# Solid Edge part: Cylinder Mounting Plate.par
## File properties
Author: davee
Template: Normal.par
Last saved by: davee
Revision: 2
Application: Solid Edge
Accuracy: 0.990
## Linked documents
Cy linder Mounting Plate.par
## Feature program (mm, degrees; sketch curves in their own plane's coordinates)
part copy "CopiedPart_1"
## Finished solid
Body 1: solid body, 41 faces, 62 edges, 12 vertices.
  Faces by surface: cylinder 22, plane 18, cone 1
  Edges by curve: circle 44, line 18
Bounding box of the edges (mm): 130.000 x 118.200 x 94.730, from (-65, 87.5, -46.5) to (65, 205.7, 48.23).
Cylindrical faces by radius (mm): R3.25 x2, R4 x2, R4.25 x6, R5.053 x1, R5.5 x2, R6 x2, R7 x6, R20 x1
Conical faces (half-angle, radius in mm at the cone's reference point): 59 deg R5.053 x1
Planar faces by outward normal: +x 1, +y 5, +z 2, -x 1, -y 8, -z 1
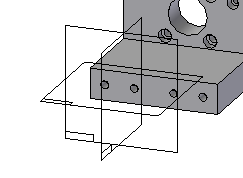
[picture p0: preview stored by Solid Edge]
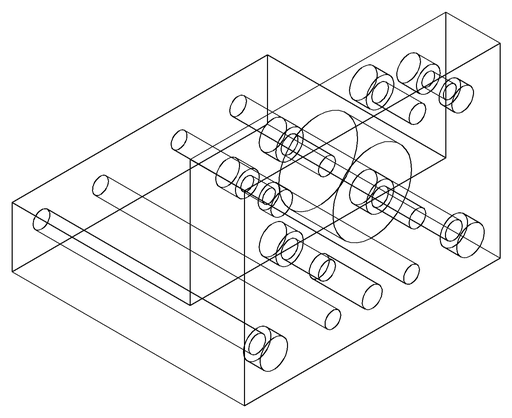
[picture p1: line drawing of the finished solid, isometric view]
